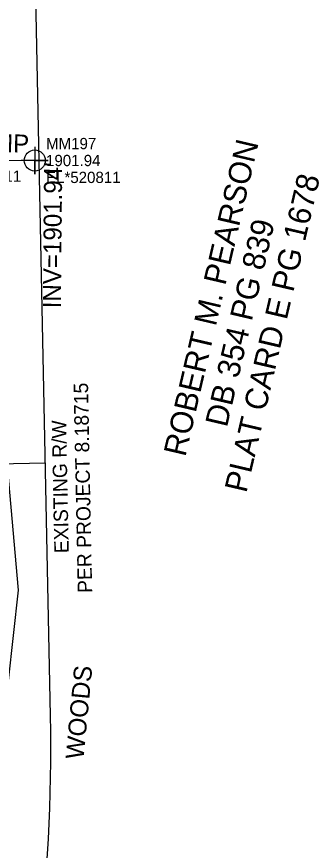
# Model space of a CAD drawing. Extents: x 1004514 to 1005247, y 553695 to 554706.
# Drawn here: x 1005067.1 to 1005134.3, y 553941.7 to 554126.5 of the extents above; entities that cross this region are included whole.
import ezdxf

# ---------------------------------------------------------------- set-up
doc = ezdxf.new("R2010")
doc.units = 0
for name, color, linetype in [('Exist Property Owner Text', 7, 'Continuous'), ('Exist Right of Way Line', 7, 'Continuous'), ('Exist Right of Way Line Text', 7, 'Continuous'), ('Exist Right of Way Width CELL', 7, 'Continuous'), ('Exist Structure Minor Pipes CMP 8 Inch', 7, 'Continuous'), ('Exist Structure Minor Pipes CMP 8 Inch Cogo Comment', 7, 'Continuous'), ('Exist Structure Minor Pipes CMP 8 Inch Cogo Elevation', 7, 'Continuous'), ('Exist Structure Minor Pipes CMP 8 Inch Cogo Number', 7, 'Continuous'), ('Exist Structure Minor Pipes CMP 8 Inch Cogo Point CELL', 7, 'Continuous'), ('Exist Structure Minor Pipes CMP 8 Inch Invert', 7, 'Continuous'), ('Exist Structure Minor Pipes CMP 8 Inch Text', 7, 'Continuous'), ('Exist Vegetation Woods Line', 7, 'Continuous'), ('Exist Vegetation Woods Line Text', 7, 'Continuous')]:
    doc.layers.add(name, color=color, linetype=linetype)

msp = doc.modelspace()

# ---------------------------------------------------------------- linework, layer by layer
at = {"layer": 'Exist Right of Way Line'}
msp.add_line((1005074.61, 553971.48), (1005071.23, 554138.95), dxfattribs=at)
msp.add_arc((1004709.69, 553964.1), 365, 344.0739, 1.1585, dxfattribs=at)
at = {"layer": 'Exist Right of Way Width CELL'}
msp.add_line((1005073.48, 554027.51), (1005014.55, 554026.32), dxfattribs=at)
at = {"layer": 'Exist Structure Minor Pipes CMP 8 Inch'}
msp.add_line((1005049.08, 554094.92), (1005071.13, 554094.65), dxfattribs=at)
at = {"layer": 'Exist Structure Minor Pipes CMP 8 Inch Cogo Point CELL'}
msp.add_lwpolyline([(1005071.13, 554097.65), (1005071.13, 554091.65), (1005071.13, 554094.65), (1005074.13, 554094.65), (1005068.13, 554094.65)], dxfattribs=at)
msp.add_circle((1005071.13, 554094.65), 2.34, dxfattribs=at)
at = {"layer": 'Exist Vegetation Woods Line'}
msp.add_lwpolyline([(1005043.25, 553870.57), (1005060.79, 553939.08), (1005067.55, 553999.39), (1005060.7, 554075.48), (1005056.83, 554134.4), (1005061.71, 554166.62), (1005070.29, 554196.97), (1005092.52, 554231.45), (1005101.44, 554246.61), (1005128.92, 554275.43)], dxfattribs=at)

# ---------------------------------------------------------------- texts
at = {"layer": 'Exist Property Owner Text'}
for s, p in [('ROBERT M. PEARSON', (1005104.54, 554028.78)), ('PLAT CARD E PG 1678', (1005118.08, 554020.77)), ('DB 354 PG 839', (1005113.77, 554035.31))]:
    msp.add_text(s, height=5, rotation=76.8585, dxfattribs=at).set_placement(p)
at = {"layer": 'Exist Right of Way Line Text'}
for s, p in [('PER PROJECT 8.18715', (1005083.88, 553998.79)), ('EXISTING R/W', (1005078.68, 554007.6))]:
    msp.add_text(s, height=3.2, rotation=91.1585, dxfattribs=at).set_placement(p)
at = {"layer": 'Exist Structure Minor Pipes CMP 8 Inch Cogo Comment'}
for s, p in [('BL*520811', (1005051.58, 554089.92)), ('EL*520811', (1005073.63, 554089.65))]:
    msp.add_text(s, height=2.5, dxfattribs=at).set_placement(p)
at = {"layer": 'Exist Structure Minor Pipes CMP 8 Inch Cogo Elevation'}
msp.add_text('1901.94', height=2.5, dxfattribs=at).set_placement((1005073.63, 554093.4))
at = {"layer": 'Exist Structure Minor Pipes CMP 8 Inch Cogo Number'}
msp.add_text('MM197', height=2.5, dxfattribs=at).set_placement((1005073.63, 554097.15))
at = {"layer": 'Exist Structure Minor Pipes CMP 8 Inch Invert'}
msp.add_text("INV=1901.94'", height=4, rotation=89.4932, dxfattribs=at).set_placement((1005076.93, 554061.85))
at = {"layer": 'Exist Structure Minor Pipes CMP 8 Inch Text'}
msp.add_text('8" CMP', height=4, rotation=359.2904, dxfattribs=at).set_placement((1005051.63, 554096.61))
at = {"layer": 'Exist Vegetation Woods Line Text'}
msp.add_text('WOODS', height=4, rotation=84.5407, dxfattribs=at).set_placement((1005081.94, 553961.74))

doc.saveas('drawing.dxf')
